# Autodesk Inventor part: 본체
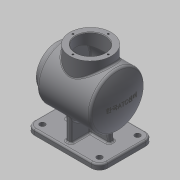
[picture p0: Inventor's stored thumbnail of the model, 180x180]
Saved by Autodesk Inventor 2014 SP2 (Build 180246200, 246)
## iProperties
Created: 2016-09
Part Number: 본체
Material: 일반
Document SubType Name: Modeling
Designer: 1sil_ho3333
Density: 1 g/cm^3
Appearance: 기본값
Author: 1sil_ho3333
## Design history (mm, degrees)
sketch "스케치2"
  geometry: L1 (-61, 0)-(61, 0); L2 (61, 0)-(61, -38); L3 (61, -38)-(49, -38); L4 (49, -38)-(49, -50); L5 (49, -50)-(-49.562, -50); A1 r 115 centre (54, 0) between (-61, 0) and (-49.562, -50); 2 further points
  constraints: 10 end point, 2 parallel, 2 perpendicular, 2 point on circle, 1 centre point, 1 coincident, 1 horizontal, 1 midpoint, 1 point on line
  dimensions: "d4" = 122 distance of L1.start L1.end; "d5" = 100 diameter of L5 L1; "d6" = 76 diameter of L3 L1; "d8" = 115 radius of A1; "d9" = 12 distance of L2.end L3.end
revolve "회전1" sketch "스케치2" stored, may be unused: angle "d10" = 90 deg
node "작업 평면1"
sketch "스케치3"
  geometry: L1 (-67.5, -50)-(67.5, -50); L2 (67.5, -50)-(67.5, 50); L3 (67.5, 50)-(-67.5, 50); L4 (-67.5, 50)-(-67.5, -50); 3 further points
  constraints: 8 end point, 2 midpoint, 2 parallel, 1 horizontal, 1 horizontal alignment, 1 perpendicular, 1 vertical alignment
  dimensions: "d12" = 100 distance of L1.end L2.end; "d13" = 135 distance of L2.end L3.end
extrude "돌출2" join sketch "스케치3" distance "d14" = 10; taper "d15" = 0 deg
node "작업 평면2"
sketch "스케치4"
  geometry: L1 (-61, -38)-(-61, 38) reference; L2 (-61, 0)-(61, 0); L3 (-61, 0)-(-61, 27); L4 (-61, 27)-(-46, 27); L5 (-46, 27)-(-46, 47); L6 (-46, 47)-(47.661, 47); L7 (-49, 50)-(49.562, 50) reference; L8 (-49, -50)-(-49, 50) reference; A1 r 115 centre (-54, 0) between (49.562, -50) and (49.562, 50) reference; A2 r 112 centre (-54, 0) between (58, 0) and (47.661, 47); 1 further point
  constraints: 10 end point, 3 point on circle, 2 perpendicular, 2 point on line, 1 centre point, 1 midpoint, 1 parallel
  dimensions: "d17" = 3 radial gap between concentric circles of A1 A2; "d18" = 3 distance between parallel lines of L7 L6; "d19" = 3 distance between parallel lines of L8 L5; "d20" = 54 diameter of L4 L2
revolve "회전2" sketch "스케치4" stored, may be unused: angle "d21" = 90 deg
fillet "모깎기1" dims "d22" = 2
chamfer "모따기1" distance "d23" = 1; stored, may be unused: second distance "d24" = 2, angle "d25" = 45 deg
sketch "스케치5"
  geometry: L1 (61, 38)-(61, -38) reference; C1 r 38 at (-1, 0); 1 further point
  constraints: 1 centre point
  dimensions: "d26" = 76 diameter of C1; "d28" = 62 distance from line of C1.centre L1
extrude "돌출3" join sketch "스케치5" stored distance "d29" = 10; taper "d30" = 0 deg
sketch "스케치6"
  geometry: C1 r 38 at (0, 0) reference; C2 r 27 at (0, 0); 1 further point
  constraints: 1 centre point, 1 coincident
  dimensions: "d31" = 54 diameter of C2
extrude "돌출4" cut sketch "스케치6" stored distance "d32" = 10; taper "d33" = 0 deg
fillet "모깎기2" dims "d34" = 5
fillet "모깎기3" dims "d35" = 3
chamfer "모따기2" distance "d36" = 1; stored, may be unused: second distance "d37" = 2, angle "d38" = 45 deg
sketch "스케치7"
  geometry: L1 (-40, -5)-(40, -5); L2 (40, -5)-(40, 5); L3 (40, 5)-(-40, 5); L4 (-40, 5)-(-40, -5); L5 (-5, -40)-(5, -40); L6 (5, -40)-(5, 40); L7 (5, 40)-(-5, 40); L8 (-5, 40)-(-5, -40); 5 further points
  constraints: 16 end point, 4 midpoint, 4 parallel, 2 horizontal, 2 horizontal alignment, 2 perpendicular, 2 vertical alignment
  dimensions: "d39" = 10 distance of L6.end L7.end; "d40" = 10 distance of L1.end L2.end; "d41" = 80 distance of L1.start L1.end; "d42" = 80 distance of L5.end L6.end
extrude "돌출6" join sketch "스케치7" stored distance "d45" = 10; taper "d46" = 0 deg
sketch "스케치8"
  geometry: L1 (-40, -72)-(-37.962, -48.7); L2 (-37.962, -48.7)-(37.962, -48.7); L3 (37.962, -48.7)-(40, -72); L4 (40, -72)-(-40, -72); L5 (67.5, -72)-(-67.5, -72) reference; L6 (-44, -50)-(46.374, -50) reference; 2 further points
  constraints: 8 end point, 2 midpoint, 1 horizontal, 1 parallel
  dimensions: "d47" = 95 deg angle of L4 L3; "d48" = 95 deg angle of L4 L1; "d49" = 1.3 distance between parallel lines of L2 L6; "d52" = 80 distance of L3.end L1.start
extrude "돌출7" join sketch "스케치8" stored distance "d50" = 10; taper "d51" = 0 deg
fillet "모깎기4" dims "d53" = 15
fillet "모깎기5" dims "d54" = 3
hole "구멍1" diameter "d57" = 10; stored, may be unused: countersink angle "d61" = 90 deg, drill point angle "d63" = 118 deg; dims "d55" = 10, "d56" = 10, "d58" = 6, "d59" = 4, "d60" = 2, "d62" = 8
fillet "모깎기6" dims "d70" = 3
fillet "모깎기7" dims "d71" = 3
sketch "스케치10" dims "d72" = 65
  geometry: L1 (0, 0)-(0, 32.5); C1 r 28 at (0, 0) reference
  constraints: 2 end point, 1 coincident, 1 vertical, 1 vertical alignment, 2 other
hole "구멍2" sketch "스케치10" at (0, 32.5) diameter "d73" = 3.242; stored, may be unused: countersink angle "d77" = 82 deg, drill point angle "d79" = 118 deg; dims "d74" = 8, "d75" = 3.023, "d76" = 2, "d78" = 10
sketch "스케치11" dims "d83" = 65
  geometry: L1 (0, 0)-(0, 32.5); C1 r 28 at (0, 0) reference; 1 further point
  constraints: 2 end point, 1 coincident, 1 vertical, 1 vertical alignment, 2 other
hole "구멍3" sketch "스케치11" at (0, 32.5) diameter "d84" = 3.242; stored, may be unused: countersink angle "d88" = 82 deg, drill point angle "d90" = 118 deg; dims "d85" = 8, "d86" = 3.023, "d87" = 2, "d89" = 10
node "작업 평면5"
sketch "스케치13"
  geometry: 2 further points
  constraints: 2 coincident, 1 other
feature "엠보싱1" sketch "스케치13" dims "d96" = 0.5, "d97" = 0
node "솔리드2"
pattern_linear "직사각형 패턴1" dims "d66" = 70, "d69" = 105
pattern_circular "원형 패턴1" dims angle "d81" = 360 deg
pattern_circular "원형 패턴2" dims angle "d92" = 360 deg
other parameters: "d11" = -82, "d16" = 147, "d95" = 131.75
